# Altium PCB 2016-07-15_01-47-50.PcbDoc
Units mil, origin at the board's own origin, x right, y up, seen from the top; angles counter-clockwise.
Board outline 1536 x 2362 mil, 4 copper layers (Top Layer, MidLayer1, MidLayer2, Bottom Layer); 21 components, 10 nets, 51 pads, 103 vias.
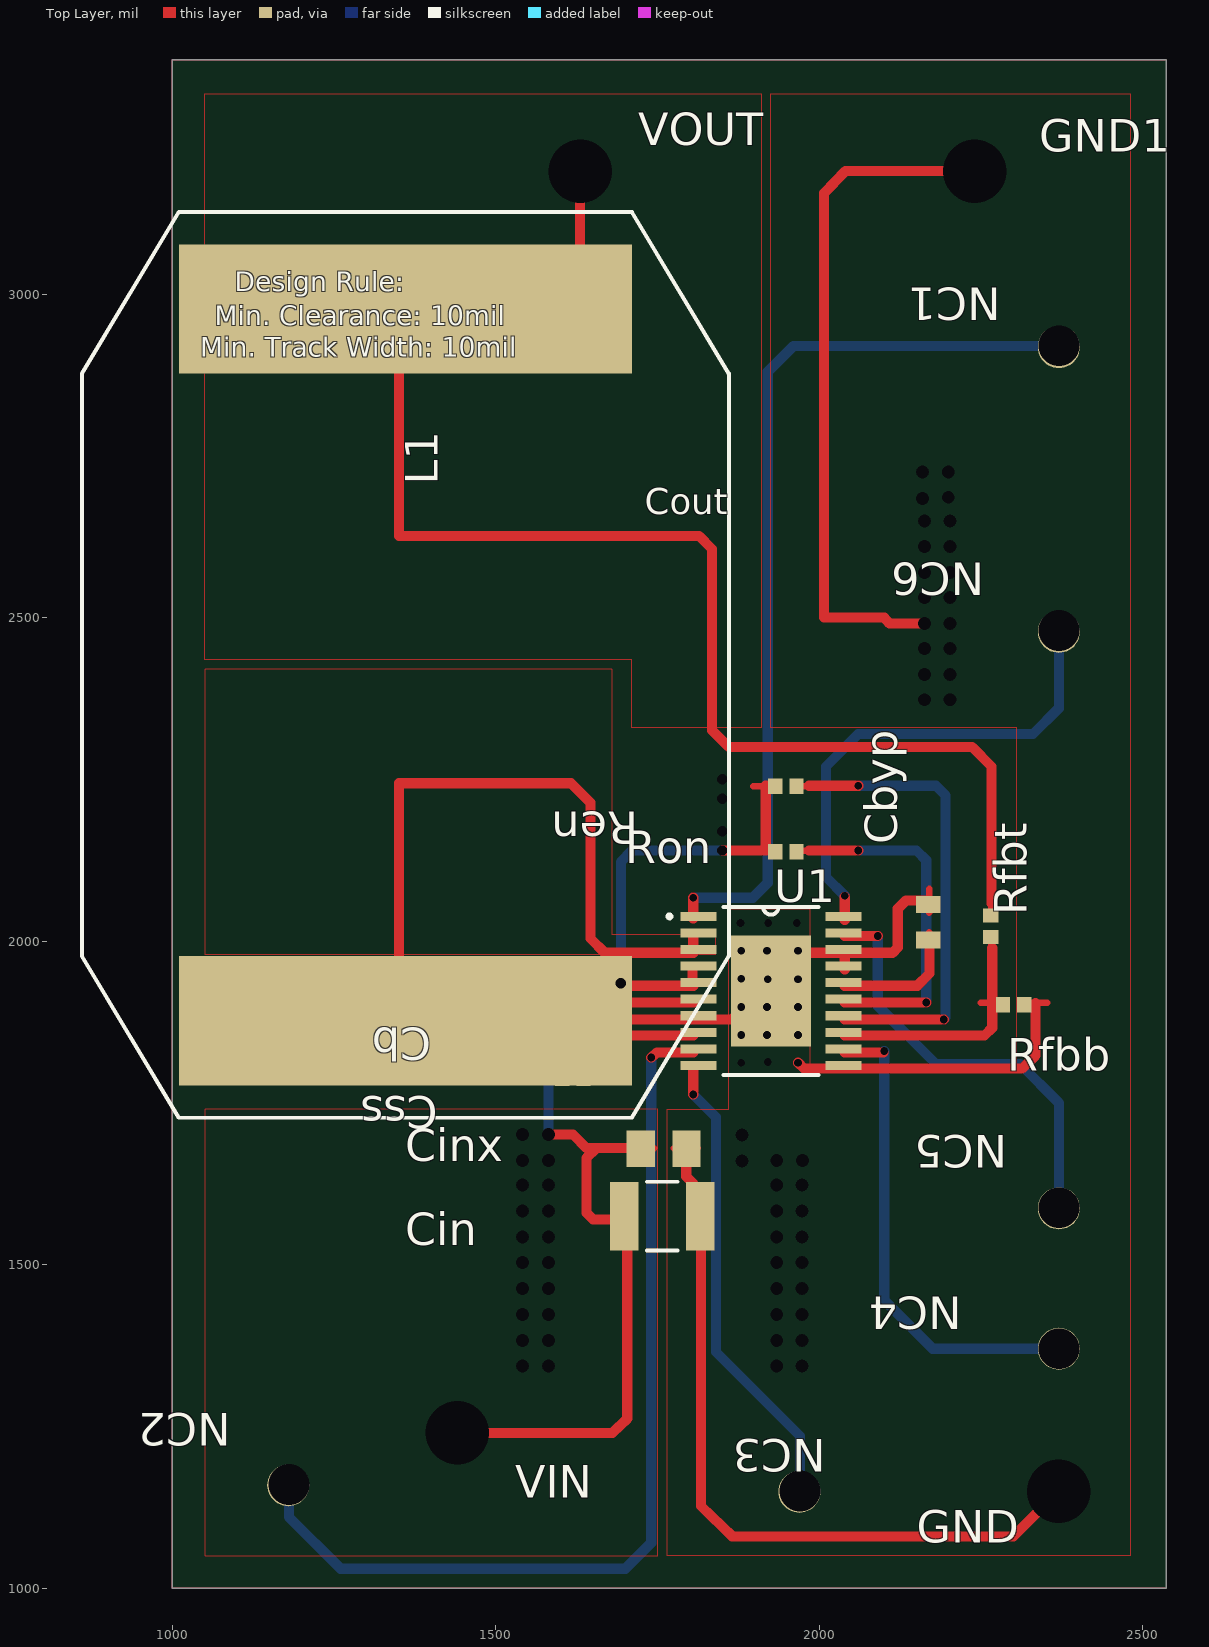
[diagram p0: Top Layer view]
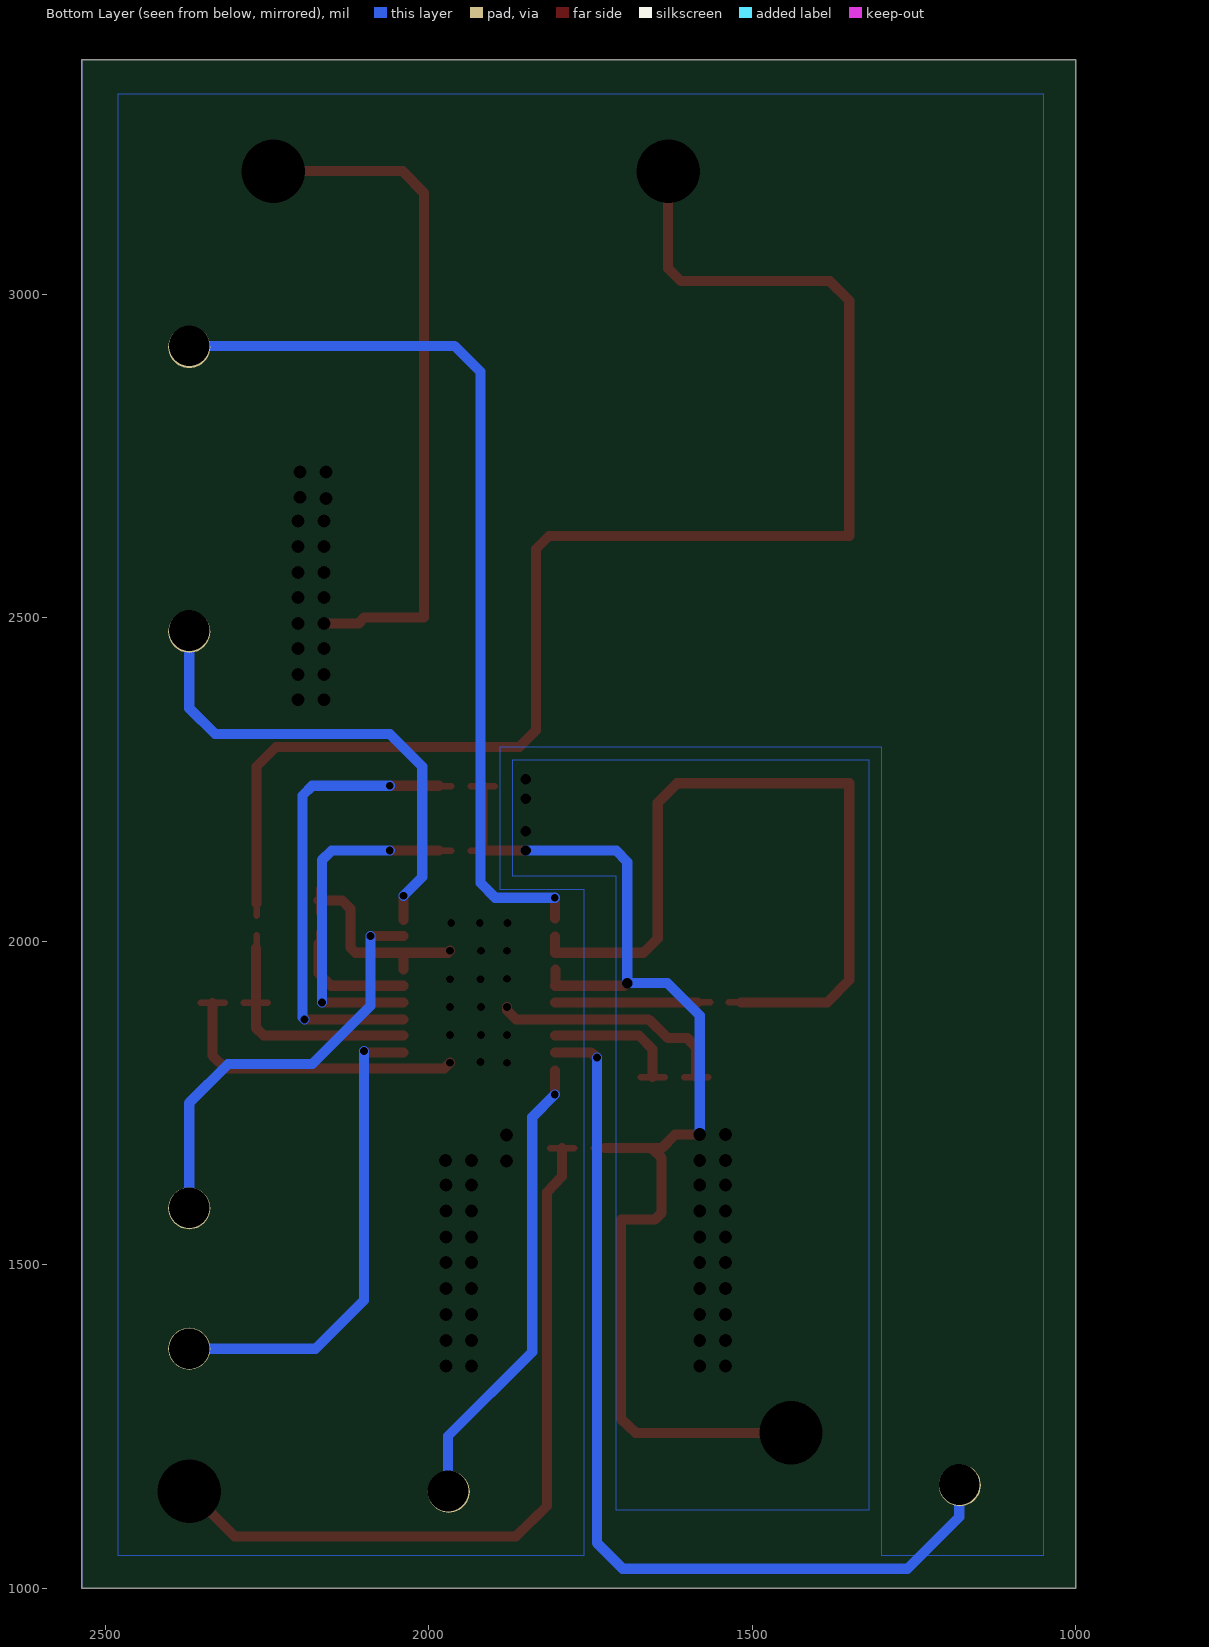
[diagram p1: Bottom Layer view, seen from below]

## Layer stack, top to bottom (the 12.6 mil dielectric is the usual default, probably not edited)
Top Layer: signal copper 1.4
Dielectric: core 12.6, FR-4, Dk 4.8
MidLayer1: signal copper 1.4
Dielectric: prepreg 12.6, FR-4, Dk 4.8
MidLayer2: signal copper 1.4
Dielectric: core 12.6, FR-4, Dk 4.8
Bottom Layer: signal copper 1.4

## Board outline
1000,1000 2536,1000 2536,3362 1000,3362

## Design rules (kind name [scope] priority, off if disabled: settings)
PlaneConnect [All] p0: scope1count=1 scope1_0_kind=Board scope1_0_value=Board scope2count=1 scope2_0_kind=Board scope2_0_value=Board commentlength=0 planeconnectstyle=Direct reliefexpansion=20 reliefentries=4 reliefconductorwidth=10 reliefairgap=10
PlaneConnect [All] p1: planeconnectstyle=Direct reliefexpansion=20 reliefentries=4 reliefconductorwidth=10 reliefairgap=10
PolygonConnect [All] p0: scope1count=1 scope1_0_kind=Board scope1_0_value=Board scope2count=1 scope2_0_kind=Board scope2_0_value=Board commentlength=0 connectstyle=Direct reliefconductorwidth=10 reliefentries=4 polygonreliefangle="90 Angle"
PolygonConnect [All] p1: connectstyle=Direct reliefconductorwidth=10 reliefentries=4 polygonreliefangle="90 Angle"

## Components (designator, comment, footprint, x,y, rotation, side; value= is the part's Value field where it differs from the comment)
Cb "" 0402 1550,1905 r180 top
Cbyp "" 0603 2168,2029 r90 top
Cin "" 1210_280 1757,1575 r0 top
Cinx "" 0805 1759,1679 r0 top
Css "" 0402 1619,1788 r180 top
GND "" TP-1502 2370,1149 r0 top
GND1 "" TP-1502 2239,3189 r0 top
L1 "" PM2120 1360,2427 r90 top
NC1 "" TP-1502 2370,2918 r180 top
NC2 "" TP-1502 1179,1159 r180 top
NC3 "" TP-1502 1969,1149 r180 top
NC4 "" TP-1502 2370,1370 r180 top
NC5 "" TP-1502 2370,1587 r180 top
NC6 "" TP-1502 2370,2478 r180 top
Ren "" 0402 1948,2239 r180 top
Rfbb "" 0402 2300,1902 r0 top
Rfbt "" 0402 2265,2023 r90 top
Ron "" 0402 1948,2138 r0 top
U1 "" MXA20A 1925,1923 r0 top
VIN "" TP-1502 1439,1240 r0 top
VOUT "" TP-1502 1629,3189 r0 top

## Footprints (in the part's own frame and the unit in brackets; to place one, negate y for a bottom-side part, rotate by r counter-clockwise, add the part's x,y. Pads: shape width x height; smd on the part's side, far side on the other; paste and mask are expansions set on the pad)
0402 [mil]
  rect 22x24 smd: 1(-16.5,0) 2(16.5,0)
0603 [mil]
  rect 26x38 smd: 1(-27.5,0) 2(27.5,0)
0805 [mil]
  rect 44x57 smd: 1(-35.5,0) 2(35.5,0)
1210_280 [mil]
  rect 44x106 smd: 1(-59,0) 2(59,0)
  silkscreen extent -24,-53 24,53
MXA20A [mil]
  rect 56x14 smd: 1(-112,115.16) 2(-112,89.57) 3(-112,63.98) 4(-112,38.39) 5(-112,12.8) 6(-112,-12.8) 7(-112,-38.39) 8(-112,-63.98) 9(-112,-89.57) 10(-112,-115.16) 11(112,-115.16) 12(112,-89.57) 13(112,-63.98) 14(112,-38.39) 15(112,-12.8) 16(112,12.8) 17(112,38.39) 18(112,63.98) 19(112,89.57) 20(112,115.16)
  rect 124x171 smd: 21(0,0)
  silkscreen extent -160,-130 74,130
PM2120 [mil]
  rect 200x700 smd: 1(-550,0) 2(550,0)
  silkscreen extent -700,-500 700,500
TP-1502 [mil]
  round 65 / inner round 0 / far side round 65 hole 32: 1(0,0)

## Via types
v1: diameter 0, hole 20, Top Layer to Bottom Layer, 60 vias
v2: diameter 0, hole 12, Top Layer to Bottom Layer, 28 vias
v3: diameter 0, hole 63, Top Layer to Bottom Layer, 6 vias
v4: diameter 0, hole 16, Top Layer to Bottom Layer, 5 vias
v5: diameter 0, hole 98, Top Layer to Bottom Layer, 4 vias

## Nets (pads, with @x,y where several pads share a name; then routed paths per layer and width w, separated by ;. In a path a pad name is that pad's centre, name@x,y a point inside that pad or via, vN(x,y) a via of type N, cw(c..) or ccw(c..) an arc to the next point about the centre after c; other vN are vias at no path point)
0: Cbyp.2 Cin.2 Cinx.2 Css.2 GND1.1 GND.1 NC1.1 NC2.1 NC3.1 NC4.1 NC5.1 NC6.1 Rfbb.2 U1.1 U1.7 U1.9 U1.10 U1.11 U1.12 U1.17 U1.18 U1.19 U1.20 U1.21 | length 9108
  Top Layer w10: Cinx.2@1775,1679.5 Cinx.2@1812,1679.5 ; Cbyp.2@2169.5,2044 2169.5,2081 ; Rfbb.2@2315,1904.5 2352,1904.5
  Top Layer w15.7: 1660,1879 1805,1879 1865,1879 1879,1893 v2(1879,1898) ; v2(1740,1820) 1749,1828 U1.9@1805,1828 ; Cinx.2@1794,1680 1794,1636 1817,1612 1817,1570 1817,1127 1865,1080 2300,1080 v5(2370,1150) ; v2(1805,1763) 1805,1800 ; U1.1@1805,2035 v2(1805,2067) ; v2(1967,1812) 1976,1803 2038,1803 2313,1803 2334,1823 2334,1904 ; v2(1967,1985) 1970,1982 U1.18@2039,1982 ; U1.12@2039,1828 2099,1828 ; U1.17@2039,1956 U1.18@2039,1982 ; U1.19@2039,2008 v2(2090,2008) ; U1.20@2039,2033 2039,2068 ; v1(2162,2491) 2108,2491 2100,2500 2007,2500 2007,3156 2040,3190 v5(2240,3190) ; Cbyp.2@2170,2063 2134,2063 2121,2050 2121,1990 2113,1982 U1.18@2039,1982
  Bottom Layer w15.7: v3(1180,1160) 1180,1110 1260,1030 1700,1030 1740,1070 v2(1740,1820) ; v2(1805,1763) 1840,1728 1840,1365 1970,1235 v3(1970,1150) ; v2(1805,2067) 1897,2067 1920,2090 1920,2880 1960,2920 v3(2370,2920) ; v2(2039,2070) 2010,2099 2010,2270 2060,2320 2330,2320 2370,2360 v3(2370,2480) ; v2(2090,2008) 2090,1900 2180,1810 2310,1810 2370,1750 v3(2370,1588) ; v2(2100,1830) 2100,1445 2175,1370 v3(2370,1370)
  other v1: 1934,1343 1973,1343 1934,1383 1973,1383 1934,1423 1973,1423 1934,1463 1973,1463 1934,1503 1973,1503 1934,1543 1973,1543 1934,1583 1973,1583 1934,1623 1973,1623 1880,1660 1934,1661 1974,1661 1880,1700 2162,2373 2202,2373 2162,2412 2202,2412 2162,2452 2202,2452 2202,2491 2162,2531 2202,2531 2162,2570 2202,2570 2162,2610 2202,2610 2162,2649 2202,2649 2159,2684 2199,2686 2159,2725 2199,2725
  other v2: 1879,1812 1920,1813 1879,1855 1919,1855 1967,1855 1919,1898 1967,1898 1920,1941 1967,1941 1879,1942 1879,1985 1919,1985 1878,2028 1921,2028 1965,2028
1: Cin.1 Cinx.1 Ren.2 Ron.1 U1.4 U1.5 VIN.1 | length 1985.4
  Top Layer w10: Cinx.1@1708,1679.5 Cinx.1@1745,1679.5 ; 1898,2139.5 Ron.1@1935,2139.5 ; 1898,2239.5 Ren.2@1935,2239.5
  Top Layer w15.7: v5(1440,1240) 1680,1240 1703,1262 1703,1570 1650,1570 1640,1580 1640,1665 1655,1680 ; v1(1581,1701) 1619,1701 1640,1680 1655,1680 ; 1698,1931 U1.5@1805,1931 ; Cinx.1@1727,1680 1655,1680 ; U1.5@1804,1932 U1.4@1804,1956 ; v4(1850,2140) 1917,2140 1917,2240
  Bottom Layer w15.7: v1(1581,1701) 1581,1885 1631,1935 v4(1693,1935) 1693,2122 1710,2140 v4(1850,2140)
  other v1: 1541,1343 1581,1343 1541,1383 1581,1383 1541,1423 1581,1423 1541,1463 1581,1463 1541,1503 1581,1503 1541,1543 1581,1543 1541,1583 1581,1583 1541,1623 1581,1623 1541,1661 1581,1661 1541,1701
  other v4: 1850,2170 1850,2220 1850,2250
2: Cbyp.1 U1.16 | length 221.9
  Top Layer w10: 2169.5,1977 Cbyp.1@2169.5,2014
  Top Layer w15.7: U1.16@2039,1931 2151,1931 2170,1950 Cbyp.1@2170,1996
3: Ren.1 U1.14 | length 754.5
  Top Layer w10: Ren.1@1965,2239.5 2002,2239.5
  Top Layer w15.7: 1984,2240 v2(2060,2240) ; U1.14@2039,1879 2191,1879 v2(2192,1879)
  Bottom Layer w15.7: v2(2060,2240) 2180,2240 2195,2225 2195,1882 v2(2192,1879)
4: Css.1 U1.8 | length 130
  Top Layer w15.7: 1675,1854 U1.8@1805,1854
5: Rfbb.1 Rfbt.1 U1.13 | length 430
  Top Layer w10: 2249,1904.5 Rfbb.1@2286,1904.5 ; 2265.5,1972 Rfbt.1@2265.5,2009
  Top Layer w15.7: U1.13@2039,1854 2255,1854 2267,1866 2267,1904 2267,1989
6: Cb.2 L1.1 U1.2 U1.3 | length 1561.3
  Top Layer w10: L1.1@1499,1905.5 Cb.2@1536,1905.5 ; L1.1@1565,1905.5 L1.1@1602,1905.5 ; L1.1@1568,1789.5 L1.1@1605,1789.5 ; L1.1@1635,1789.5 L1.1@1672,1789.5
  Top Layer w15.7: L1.1@1517,1905 1384,1905 1350,1940 1350,2244 1616,2244 1646,2214 1646,2004 1668,1982 1805,1982 U1.2@1805,2007 ; L1.1@1587,1790 1587,1836 1600,1850 1630,1850 L1.1@1660,1879 ; L1.1@1654,1790 1654,1833 L1.1@1675,1854 ; L1.1@1693,1935 L1.1@1698,1931
7: L1.2 Rfbt.2 VOUT.1 | length 2291.2
  Top Layer w10: Rfbt.2@2265.5,2039 2265.5,2076
  Top Layer w15.7: v5(1630,3190) 1630,3040 1610,3020 1380,3020 1350,2990 1350,2626 1814,2626 1834,2606 1834,2500 1834,2326 1860,2300 2236,2300 2266,2270 2266,2058
8: Cb.1 U1.6 | length 220
  Top Layer w15.7: 1585,1905 U1.6@1805,1905
9: Ron.2 U1.15 | length 570.2
  Top Layer w10: Ron.2@1965,2139.5 2002,2139.5
  Top Layer w15.7: 1984,2140 v2(2060,2140) ; U1.15@2039,1905 v2(2165,1905)
  Bottom Layer w15.7: v2(2060,2140) 2150,2140 2165,2125 v2(2165,1905)

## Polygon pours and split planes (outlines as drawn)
7 on Top Layer " " (solid, pour order 1): 1910,2330 1710,2330 1710,2435 1050,2435 1050,3310 1910,3310
1 on Top Layer " " (solid, pour order 2): 1750,1740 1050,1740 1050,1050 1750,1050
6 on Top Layer " " (solid, pour order 3): 1840,2010 1680,2010 1680,2420 1050,2420 1050,1980 1840,1980
0 on Top Layer " " (solid, pour order 5): 1860,2050 1985,2050 1985,1810 2305,1810 2305,2330 1925,2330 1925,3310 2480,3310 2480,1050 1765,1050 1765,1740 1860,1740
1 on Bottom Layer " " (solid, pour order 0): 1870,2280 1320,2280 1320,1120 1710,1120 1710,2100 1870,2100
0 on Bottom Layer " " (solid, pour order 4): 1050,3310 1050,1050 1300,1050 1300,2300 1890,2300 1890,2080 1760,2080 1760,1050 2480,1050 2480,3310

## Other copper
Multi-Layer:
  the board outline again, w1

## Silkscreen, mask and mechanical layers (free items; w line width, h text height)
Top Overlay:
  text "Design Rule:" at 1096,3004 h30
  text "Min. Clearance: 10mil" at 1065,2952 h30
  text "Min. Track Width: 10mil" at 1043,2903 h30
  text "Cout" at 1730,2660 h40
